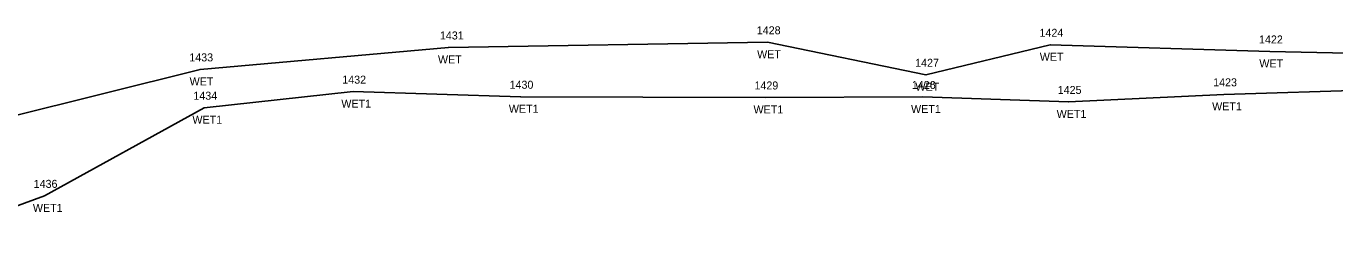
# Model space of a CAD drawing. Extents: x 1967699 to 1968370, y 1117733 to 1117905.
# Drawn here: x 1968035.2 to 1968198.7, y 1117877.9 to 1117905.4 of the extents above; entities that cross this region are included whole.
import ezdxf

# ---------------------------------------------------------------- set-up
doc = ezdxf.new("R2010")
doc.units = 0
for name, color, linetype in [('RD_EX_H2O_WetLd', 7, 'Continuous'), ('RD_EX_H2O_WetLd_txCode', 7, 'Continuous'), ('RD_SMD_Locator', 7, 'Continuous')]:
    doc.layers.add(name, color=color, linetype=linetype)

msp = doc.modelspace()

# ---------------------------------------------------------------- linework, layer by layer
at = {"layer": 'RD_EX_H2O_WetLd'}
for points in [[(1968367.53, 1117902.43), (1968362.98, 1117898.55), (1968347.35, 1117899.48), (1968328.86, 1117899.6), (1968318.21, 1117897.51), (1968292.87, 1117899.07), (1968277.7, 1117898.66), (1968253.32, 1117900.14), (1968234.81, 1117900.5), (1968208.25, 1117901.82), (1968190.62, 1117902.21), (1968163.17, 1117903.04), (1968147.64, 1117899.29), (1968127.85, 1117903.36), (1968087.96, 1117902.71), (1968056.92, 1117899.97), (1968032.7, 1117893.9)], [(1968362.05, 1117892.46), (1968347.73, 1117893.23), (1968331.65, 1117894.12), (1968319.19, 1117892.86), (1968302.77, 1117895.12), (1968292.25, 1117895.64), (1968277.54, 1117893.78), (1968251.35, 1117895.61), (1968232.27, 1117895.94), (1968203.56, 1117897.42), (1968184.88, 1117896.85), (1968165.45, 1117895.9), (1968147.25, 1117896.52), (1968127.56, 1117896.46), (1968096.98, 1117896.55), (1968076.04, 1117897.19), (1968057.43, 1117895.18), (1968037.49, 1117884.16), (1968020.4, 1117877.91)]]:
    msp.add_lwpolyline(points, dxfattribs=at)
at = {"layer": 'RD_SMD_Locator'}
for centre in [(1968087.96, 1117902.71), (1968127.85, 1117903.36), (1968163.17, 1117903.04), (1968190.62, 1117902.21), (1968056.92, 1117899.97), (1968147.64, 1117899.29), (1968076.04, 1117897.19), (1968096.98, 1117896.55), (1968127.56, 1117896.46), (1968147.25, 1117896.52), (1968184.88, 1117896.85), (1968057.43, 1117895.18), (1968165.45, 1117895.9), (1968037.49, 1117884.16)]:
    msp.add_circle(centre, 0.001, dxfattribs=at)

# ---------------------------------------------------------------- texts
at = {"layer": 'RD_EX_H2O_WetLd_txCode'}
for s, p in [('1431', (1968086.89, 1117903.71)), ('1428', (1968126.5, 1117904.36)), ('1424', (1968161.83, 1117904.04)), ('1422', (1968189.27, 1117903.21)), ('1433', (1968055.57, 1117900.97)), ('WET', (1968086.65, 1117900.71)), ('WET', (1968126.54, 1117901.36)), ('1427', (1968146.29, 1117900.29)), ('WET', (1968161.87, 1117901.04)), ('WET', (1968189.31, 1117900.21)), ('WET', (1968055.61, 1117897.97)), ('1432', (1968074.69, 1117898.19)), ('1430', (1968095.6, 1117897.55)), ('1429', (1968126.21, 1117897.46)), ('1426', (1968145.88, 1117897.52)), ('WET', (1968146.33, 1117897.29)), ('1425', (1968164.11, 1117896.9)), ('1423', (1968183.54, 1117897.85)), ('1434', (1968056.08, 1117896.18)), ('WET1', (1968074.57, 1117895.19)), ('WET1', (1968095.51, 1117894.55)), ('WET1', (1968126.09, 1117894.46)), ('WET1', (1968145.78, 1117894.52)), ('WET1', (1968163.98, 1117893.9)), ('WET1', (1968183.41, 1117894.85)), ('WET1', (1968055.96, 1117893.18)), ('1436', (1968036.12, 1117885.16)), ('WET1', (1968036.02, 1117882.16))]:
    msp.add_text(s, height=1, dxfattribs=at).set_placement(p)

doc.saveas('drawing.dxf')
